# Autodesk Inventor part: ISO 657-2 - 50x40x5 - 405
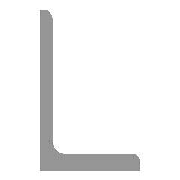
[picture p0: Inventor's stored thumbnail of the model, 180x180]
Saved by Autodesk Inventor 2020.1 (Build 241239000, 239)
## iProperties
IsCustomPart: 1
_CCFamilyMember: 8
_CCFamilyDisplayName: ISO 657/2 - 1989 - Warm gewalzter Winkelstahl, ungleichschenklig
_FrameMemberDoc: Frame Member File
_Version: 15.0.0
_GetPNFromCC: 1
Created: 2019-01
Part Number: ISO 657-2 - 50x40x5 - 405
Material: Stahl, weich
Description: Warm gewalzter Winkelstahl, ungleichschenklig
Document SubType Name: Modeling
Standard: ISO
Designer: lutzd
Standard Revision: First edition 1989-08-01
Standards Organization: ISO
Language: de-DE
Size Designation: 50x40x5
Categories: <MemberInstance><Categories><Category DisplayName="Profile" InternalName="089c4875-fa83-4c05-b084-43b9cc11f5ed" Mnemonic="GRDR"><CategoryParameter DisplayName="
Stock Number: 50x40x5
Mass: 1268.04 g
Surface Area: 671.577 cm^2
Volume: 161.534 cm^3
Density: 7.85 g/cm^3
Appearance: Semi-Polished(8)
G_L: 405,000 mm
G_W: 40,000 mm
G_H: 50,000 mm
DocNumber: ADSK-014324
Folder: .
Dimensions: 40x50x405 mm
Mass: 1,268 kg
Title: Profil-Bauteil
Author: lutzd
Revision Number: -
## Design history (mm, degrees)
node "Startebene"
node "Endebene"
sketch "Skizze"
  geometry: L1 (48.6, -10.5)-(20.6, -10.5); L2 (10.6, -15.5)-(50.6, -15.5); L3 (50.6, -15.5)-(50.6, -12.5); L4 (-7.041, 0)-(21.538, 0); L5 (15.6, -5.5)-(15.6, 32.5); L6 (10.6, 34.5)-(10.6, -15.5); L7 (13.6, 34.5)-(10.6, 34.5); L8 (0, -8.041)-(0, 34.538); L9 (0, 44.997)-(0, -25.583) reference; L10 (-18.653, 0)-(62.625, 0) reference; A1 r 5 centre (20.6, -5.5) between (15.6, -5.5) and (20.6, -10.5); A2 r 2 centre (48.6, -12.5) between (50.6, -12.5) and (48.6, -10.5); A3 r 2 centre (13.6, 32.5) between (15.6, 32.5) and (13.6, 34.5); 3 further points
  constraints: 16 end point, 6 point on circle, 6 point on line, 6 tangent, 3 centre point, 2 collinear, 2 parallel, 1 equal radius
  dimensions: "d12" = 5 distance between parallel lines of L5 L6 (= G_T); "d13" = 50 distance of L6.start L2.start (= G_H); "d14" = 40 distance of L2.start L2.end (= G_W); "d15" = 15.5 distance between parallel lines of L4 L2 (= ex); "d16" = 5 distance between parallel lines of L2 L1 (= G_T); "d17" = 10.6 distance between parallel lines of L8 L6 (= ey); "d18" = 5 radius of A1 (= G_IR); "d19" = 2 radius of A2 (= G_ER)
extrude "Körper" new body sketch "Skizze" stored distance "d4" = 405 (= G_L); taper "d5" = 0 deg
node "Driven Length"
  sketch "Sketch3"
    geometry: L1 (0, 0)-(10, 0) reference
    constraints: 2 end point, 1 horizontal
  workplane "Work Plane3"
  sketch "Sketch4"
    geometry: L1 (-2, 0)-(12, 0) reference; L2 (-2, 405)-(12, 405) reference
    dimensions: "d23" = 405 distance between parallel lines of L1 L2 (derived)
sketch "Skizze5"
  geometry: L1 (0, -50)-(0, 0) reference; L2 (0, -50)-(405, -50) reference; L3 (405, -50)-(405, 0) reference; L4 (0, 0)-(405, 0) reference; L5 (0, -37.5)-(64.952, 0); L6 (405, -37.5)-(340.048, 0); 1 further point
  constraints: 4 end point, 4 point on line, 1 horizontal alignment
  dimensions: "d24" = 12.5 distance from line of L6.start L2; "d25" = 60 deg angle of L3 L6; "d26" = 60 deg angle of L1 L5 (= d25)
extrude "Extrusion2" cut sketch "Skizze5" distance "d27" = 10; taper "d28" = 0 deg
body "Solid1"
other parameters: "G_W" = 40 [user parameter; used in 1 equation term], "G_H" = 50 [user parameter; used in 1 equation term], "G_T" = 5 [user parameter; used in 2 equation terms], "G_ER" = 2 [user parameter; used in 1 equation term], "G_IR" = 5 [user parameter; used in 1 equation term], "G_L" = 405 (= d23) [user parameter; used in 1 equation term], "ex" = 15.5 [user parameter; used in 1 equation term], "ey" = 10.6 [user parameter; used in 1 equation term], "G_OFFSET_START" = 0 [user parameter; used in 1 equation term], "G_OFFSET_END" = 0 [user parameter; used in 1 equation term], "d20" = 0 (computed from G_OFFSET_START), "d21" = 405 (= G_OFFSET_END + B_L), "B_L" = 405 [user parameter; used in 1 equation term], "d22" = 90 deg
